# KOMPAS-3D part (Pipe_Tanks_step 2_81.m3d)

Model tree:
1. X Axis
2. Y Axis
3. Z Axis  (labels: T-Bend Dn 50; Pipe Dn 50)
     Òîëùèíà ñòåíêè 1 = 1

Referenced files in C:\Documents and Settings\kashirsky\Мои документы\Camtasia Studio\Pipelines3D\Tanks\: Tanks_step 4.a3d
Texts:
  Pipe Dn 50
  Steel ASTM A295
  Three Point Plane
  Plane at Angle
  Line and Point Plane
  Axis through Two Vertices
  Axis of Feature
  Axis of Conical Surface
  Axis through Edge
  Trim by Surface
  Trim by Sketch
  Feature with No History
  Intersection Axis of Two Planes
  Two Line Plane
  Line and Face Plane
  Bend by line
  Hole in sheet body
  Cut in sheet body
  Point in CM
  Linear Dimension from Line to Point
  Surface Finish Symbol
  Geometric Tolerance Symbol
  Leader #1
  Leader #2
  Leader #3
  Shape Deviations and Datum
  Node point number
  Mark of coordination axis
  Node point designation
  Mark/Reference designation with leader
  Mark/reference designation on line
  Mark/Reference designation without leader
  T-Bend Dn 50
  Plane of section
